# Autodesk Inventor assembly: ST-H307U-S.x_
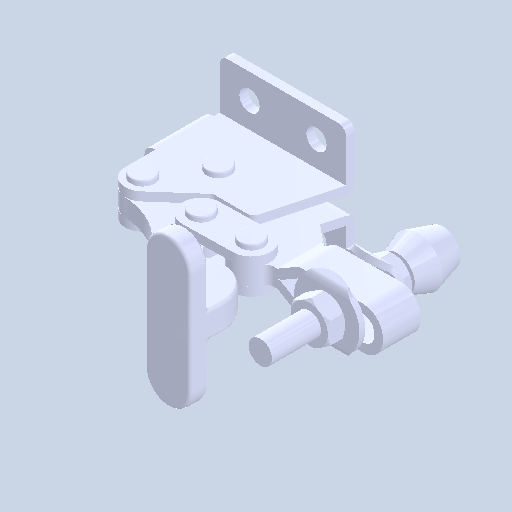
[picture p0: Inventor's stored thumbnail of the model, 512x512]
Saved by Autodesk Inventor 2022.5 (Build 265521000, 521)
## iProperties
Created: 2024-07
Part Number: ST-H307U-S.x_
Document SubType Name: Assembly
Designer: ImaoCorp
Author: ImaoCorp
Sending System: SOLIDWORKS 2022-2022290
MC: AMD64
MC_MODEL: Intel64 Family 6 Model 60 Stepping 3, GenuineIntel
OS: Windows_NT
FRU: Parasolid Version 33.1, build 260,  4-25-2022
FORMAT: text
GUISE: transmit
KEY: FILEST-H307U-S.x_t
DATE: Mon Jul 29 10:02:51 2024
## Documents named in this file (8)
- X:\14_SW2022-Inv2022\07_2024-10新製品(WHS)\OTC_データ\s\st-h307u-s\ST-H307U-S.x_.iam
- X:\14_SW2022-Inv2022\07_2024-10新製品(WHS)\OTC_データ\s\st-h307u-s\ST-H307U-S_01.ipt
- X:\14_SW2022-Inv2022\07_2024-10新製品(WHS)\OTC_データ\s\st-h307u-s\ST-H307U-S_02.ipt
- X:\14_SW2022-Inv2022\07_2024-10新製品(WHS)\OTC_データ\s\st-h307u-s\ST-H307U-S_03.ipt
- X:\14_SW2022-Inv2022\07_2024-10新製品(WHS)\OTC_データ\s\st-h307u-s\ST-H307U-S_04.ipt
- X:\14_SW2022-Inv2022\07_2024-10新製品(WHS)\OTC_データ\s\st-h307u-s\ST-H307U-S_05.ipt
- X:\14_SW2022-Inv2022\07_2024-10新製品(WHS)\OTC_データ\s\st-h307u-s\ST-H307U-S_06.ipt
- X:\14_SW2022-Inv2022\07_2024-10新製品(WHS)\OTC_データ\s\st-h307u-s\ST-H307U-S_07.ipt
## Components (7 placed, 7 different names)
1. ST-H307U-S_01
2. ST-H307U-S_02
3. ST-H307U-S_03
4. ST-H307U-S_04
5. ST-H307U-S_05
6. ST-H307U-S_06
7. ST-H307U-S_07
